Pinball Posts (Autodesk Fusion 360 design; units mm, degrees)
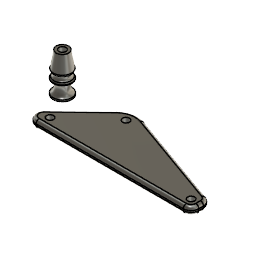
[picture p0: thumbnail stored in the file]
sketch "Large" plane through (0, 0, 0) normal (1, 0, 0) x axis (0, 1, 0)
  line L1 (10, 0) -> (0, 0)
  line L2 (0, 25) -> (5, 25)
  line L3 (0, 0) -> (0, 25)
  line L4 (5, 25) -> (9.7345, 14.9168)
  line L5 (10, 14) -> (10, 13.9365)
  line L6 (10, 1) -> (10, 0)
  line L7 (10, 9.4019) -> (10, 9)
  arc A1 centre (10.5, 12) radius 2 clockwise from (9.5, 10.2679) to (9.3862, 13.6612)
  arc A2 centre (8.8294, 14.4918) radius 1 clockwise from (9.7345, 14.9168) to (9.3862, 13.6612)
  arc A3 centre (9, 9.4019) radius 1 clockwise from (9.5, 10.2679) to (10, 9.4019)
  arc A4 centre (13, 5) radius 5 clockwise from (10, 1) to (10, 9)
  point P1 (0, 0)
  point P2 (0, 0)
  point P6 (0, 0)
  point P9 (10, 13.9365)
  point P18 (10, 9)
  coincident P1 P2
  horizontal L1
  parallel L1 L2
  coincident P1 P6
  perpendicular L1 L3
  perpendicular L1 L6
  coincident P9 L6
  collinear L5 L6
  tangent L4 A2
  tangent A1 A2
  tangent A1 A3
  tangent A3 L6
  coincident P18 L6
  collinear L6 L7
  dimension "d2" radius A2 = 1
  dimension "d3" radius A3 = 1
revolve "Revolve1" sketch "Large" AlongAngle 360 bodies "Large"
sketch "Large Top" plane through (0, 0, 25) normal (0, 0, 1) x axis (-1, 0, 0)
  circle C1 centre (0, 0) radius 5
  circle C2 centre (0, 0) radius 2.25
  point P1 (0, 0)
  point P3 (0, 0)
  coincident P1 P3
sketch "Thin" plane through (0, 0, 0) normal (1, 0, 0) x axis (0, 1, 0)
  line L1 (6, 0) -> (0, 0)
  line L2 (6, 9.4019) -> (6, 9)
  line L3 (6, 1) -> (6, 0)
  line L4 (6, 14) -> (6, 13.9365)
  line L5 (4, 25) -> (5.8143, 14.6647)
  line L6 (0, 0) -> (0, 25)
  line L7 (0, 25) -> (4, 25)
  line L8 (36, 14) -> (36, 13.9365)
  line L9 (36, 1) -> (36, 0)
  line L10 (36, 0) -> (30, 0)
  line L11 (30, 25) -> (34, 25)
  line L12 (30, 0) -> (30, 25)
  line L13 (36, 9.4019) -> (36, 9)
  line L14 (35.546, 18.1525) -> (34, 25)
  arc A1 centre (6.5, 12) radius 2 clockwise from (5.5, 10.2679) to (5.3862, 13.6612)
  arc A2 centre (5, 9.4019) radius 1 clockwise from (5.5, 10.2679) to (6, 9.4019)
  arc A3 centre (4.8294, 14.4918) radius 1 clockwise from (5.8143, 14.6647) to (5.3862, 13.6612)
  arc A4 centre (9, 5) radius 5 clockwise from (6, 1) to (6, 9)
  arc A5 centre (35, 9.4019) radius 1 clockwise from (35.5, 10.2679) to (36, 9.4019)
  arc A6 centre (39, 5) radius 5 clockwise from (36, 1) to (36, 9)
  arc A7 centre (36.5, 16) radius 2 clockwise from (35.0093, 14.6667) to (35.3466, 17.6339)
  arc A8 centre (36.5, 12) radius 2 clockwise from (35.5, 10.2679) to (35.0093, 13.3333)
  arc A9 centre (34.2639, 14) radius 1 clockwise from (35.0093, 14.6667) to (35.0093, 13.3333)
  arc A10 centre (35.0583, 18.0424) radius 0.5 clockwise from (35.546, 18.1525) to (35.3466, 17.6339)
  point P17 (0, 0)
  point P19 (0, 0)
  point P9 (0, 0)
  point P6 (6, 13.9365)
  point P2 (6, 9)
  point P21 (30, 0)
  point P32 (30, 0)
  point P25 (30, 0)
  point P29 (36, 13.9365)
  point P22 (36, 9)
  coincident P17 P19
  horizontal L1
  parallel L1 L7
  coincident P9 P19
  perpendicular L1 L6
  perpendicular L1 L3
  coincident P6 L3
  collinear L3 L4
  tangent A3 L5
  tangent A1 A3
  tangent A1 A2
  tangent A2 L3
  coincident P2 L3
  collinear L2 L3
  coincident P21 P32
  horizontal L10
  parallel L10 L11
  coincident P21 P25
  perpendicular L10 L12
  perpendicular L9 L10
  coincident P29 L9
  collinear L8 L9
  tangent A5 L9
  coincident P22 L9
  collinear L9 L13
  tangent A8 A9
  tangent A7 A9
  tangent A7 A10
  tangent L14 A10
  dimension "d8" radius A3 = 1
  dimension "d9" radius A2 = 1
  dimension "d51" radius A5 = 1
  dimension "d52" diameter A8 = 4
  dimension "d53" diameter A7 = 4
  dimension "d55" radius A9 = 1
  dimension "d58" radius A10 = 0.5
revolve "Revolve2" sketch "Thin" AlongAngle 360 bodies "Thin"
move "Move1"
extrude "Extrude2" cut sketch "Large Top" profile of C2 against normal blind 30
sketch "Thin Top" plane through (0, 0, 25) normal (0, 0, 1) x axis (-1, 0, 0)
  circle C1 centre (0, -22) radius 4
  circle C2 centre (0, -22) radius 2.25
  concentric C1 C2
  dimension "d13" diameter C2 = 4.5
extrude "Extrude3" cut sketch "Thin Top" profile of C2 against normal blind 30
sketch "Top" plane through (0, 0, 0) normal (0, 0, 1) x axis (1, 0, 0)
  line L1 (106, -6) -> (11.0112, -6)
  line L2 (111, 2.0464) -> (111, -1)
  line L3 (45.8464, 28.7804) -> (107.6777, 6.7565)
  line L4 (7.5379, 2.5967) -> (31.4235, 25.6628)
  arc A1 centre (106, -1) radius 5 clockwise from (111, -1) to (106, -6)
  arc A2 centre (106, 2.0464) radius 5 clockwise from (107.6777, 6.7565) to (111, 2.0464)
  circle C1 centre (105, 0) radius 2.25
  circle C2 centre (40, 23) radius 2.25
  circle C3 centre (40, 23) radius 4
  circle C4 centre (105, 0) radius 4
  circle C5 centre (14, 0) radius 2.25
  circle C6 centre (14, 0) radius 4
  arc A3 centre (41.1488, 15.5921) radius 14 clockwise from (31.4235, 25.6628) to (45.8464, 28.7804)
  arc A4 centre (11.0112, -1) radius 5 clockwise from (11.0112, -6) to (7.5379, 2.5967)
  perpendicular L1 L2
  tangent L1 A1
  tangent L2 A1
  tangent L2 A2
  tangent L3 A2
  concentric C2 C3
  concentric C1 C4
  tangent L3 A3
  tangent L4 A3
  tangent L4 A4
  tangent L1 A4
  dimension "d16" radius A1 = 5
  dimension "d19" radius A2 = 5
  dimension "d32" diameter C3 = 8
  dimension "d33" diameter C4 = 8
  dimension "d37" diameter C6 = 8
  dimension "d38" radius A3 = 14
  dimension "d39" radius A4 = 5
extrude "Extrude4" new body sketch "Top" profile of L1 L2 L3 A1 A2 C1 C2 along normal blind 5 bodies "Top R"
fillet "Fillet1" radius 2
fillet "Fillet2" radius 2
mirror "Mirror1" mirrorStitchTolerance 0.1 bodies "Top L"
extrude "Extrude5" cut sketch "Top" profile of C5 along normal blind 10
extrude "Extrude6" cut sketch "Top" profile of C5 along normal blind 10
sketch "Thin Short" plane through (0, 0, 0) normal (1, 0, 0) x axis (0, 1, 0)
  line L1 (0, 0) -> (0, 17)
  line L2 (0, 17) -> (4, 17)
  line L3 (6, 14) -> (6, 13.9365)
  line L4 (4, 17) -> (5.5893, 15.1417)
  line L5 (6, 9.4019) -> (6, 9)
  line L6 (6, 1) -> (6, 0)
  line L7 (6, 0) -> (0, 0)
  arc A1 centre (5, 9.4019) radius 1 clockwise from (5.5, 10.2679) to (6, 9.4019)
  arc A2 centre (9, 5) radius 5 clockwise from (6, 1) to (6, 9)
  arc A3 centre (6.5, 12) radius 2 clockwise from (5.5, 10.2679) to (5.3862, 13.6612)
  arc A4 centre (4.8294, 14.4918) radius 1 clockwise from (5.5893, 15.1417) to (5.3862, 13.6612)
  point P5 (0, 0)
  point P6 (0, 0)
  point P13 (0, 0)
  point P14 (6, 13.9365)
  point P19 (6, 9)
  coincident P5 P6
  horizontal L7
  parallel L2 L7
  coincident P6 P13
  perpendicular L1 L7
  perpendicular L6 L7
  coincident P14 L6
  collinear L3 L6
  tangent L4 A4
  tangent A3 A4
  tangent A1 A3
  tangent A1 L6
  coincident P19 L6
  collinear L5 L6
  dimension "d44" radius A4 = 1
  dimension "d45" radius A1 = 1
revolve "Revolve3" sketch "Thin Short" AlongAngle 360 bodies "Thin Short"
sketch "Sketch7" plane through (0, 0, 17) normal (0, 0, 1) x axis (-1, 0, 0)
  circle C1 centre (0, 0) radius 4
  circle C2 centre (0, 0) radius 2.25
  circle C3 centre (0, -30) radius 2.25
  point P1 (0, 0)
  point P3 (0, 0)
  coincident P1 P3
  dimension "d47" diameter C2 = 4.5
  dimension "d56" diameter C3 = 4.5
extrude "Extrude7" cut sketch "Sketch7" profile of C2 against normal blind 30
revolve "Revolve4" sketch "Thin" AlongAngle 360 bodies "Double Rope"
extrude "Extrude8" cut sketch "Sketch7" profile of C3 along normal blind 20 and against normal blind 30
sketch "Square Rope Kicker" plane through (0, 0, 0) normal (1, 0, 0) x axis (0, 1, 0)
  line L1 (30, 0) -> (30, 25)
  line L2 (35.2972, 16.91) -> (34, 25)
  line L3 (36, 1) -> (36, 0)
  line L4 (6, 14) -> (6, 13.9365)
  line L5 (36, 14) -> (36, 13.9365)
  line L6 (0, 25) -> (4, 25)
  line L7 (6, 9.4019) -> (6, 9)
  line L8 (36, 0) -> (30, 0)
  line L9 (6, 1) -> (6, 0)
  line L10 (0, 0) -> (0, 25)
  line L11 (4, 25) -> (5.8143, 14.6647)
  line L12 (6, 0) -> (0, 0)
  line L13 (30, 25) -> (34, 25)
  line L14 (33.6, 15.0235) -> (33.6, 8.7461)
  line L15 (34.2826, 15.2469) -> (33.6, 15.0235)
  line L16 (34.0349, 8.6771) -> (33.6, 8.7461)
  arc A1 centre (6.5, 12) radius 2 clockwise from (5.5, 10.2679) to (5.3862, 13.6612)
  arc A2 centre (9, 5) radius 5 clockwise from (6, 1) to (6, 9)
  arc A3 centre (4.8294, 14.4918) radius 1 clockwise from (5.8143, 14.6647) to (5.3862, 13.6612)
  arc A4 centre (5, 9.4019) radius 1 clockwise from (5.5, 10.2679) to (6, 9.4019)
  arc A5 centre (40.5476, 4.5283) radius 5.7559 clockwise from (36, 1) to (35.1948, 6.6442)
  arc A6 centre (33.7998, 7.1957) radius 1.5 clockwise from (34.0349, 8.6771) to (35.1948, 6.6442)
  arc A7 centre (33.8161, 16.6725) radius 1.5 clockwise from (35.2972, 16.91) to (34.2826, 15.2469)
  point P8 (0, 0)
  point P11 (0, 0)
  point P21 (0, 0)
  point P16 (6, 13.9365)
  point P14 (6, 9)
  point P2 (30, 0)
  point P25 (30, 0)
  point P4 (30, 0)
  point P24 (36, 13.9365)
  coincident P8 P11
  horizontal L12
  parallel L6 L12
  coincident P11 P21
  perpendicular L10 L12
  perpendicular L9 L12
  coincident P16 L9
  collinear L4 L9
  tangent A3 L11
  tangent A1 A3
  tangent A1 A4
  tangent L9 A4
  coincident P14 L9
  collinear L7 L9
  coincident P2 P25
  horizontal L8
  parallel L8 L13
  coincident P2 P4
  perpendicular L1 L8
  perpendicular L3 L8
  coincident P24 L3
  collinear L3 L5
  parallel L1 L14
  tangent L16 A6
  tangent A5 A6
  tangent L15 A7
  tangent L2 A7
  dimension "d63" radius A3 = 1
  dimension "d64" radius A4 = 1
  dimension "d70" radius A6 = 1.5
  dimension "d71" radius A7 = 1.5
revolve "Revolve5" sketch "Square Rope Kicker" AlongAngle 360 bodies "Square Rope kicker"
extrude "Extrude9" cut sketch "Sketch7" profile of C3 along normal blind 20 and against normal blind 20
extrude "Extrude1" cut sketch "Large Top" profile of C2 against normal blind 30
named bodies: "Large", "Thin", "Top R", "Top L", "Thin Short", "Double Rope", "Square Rope kicker"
